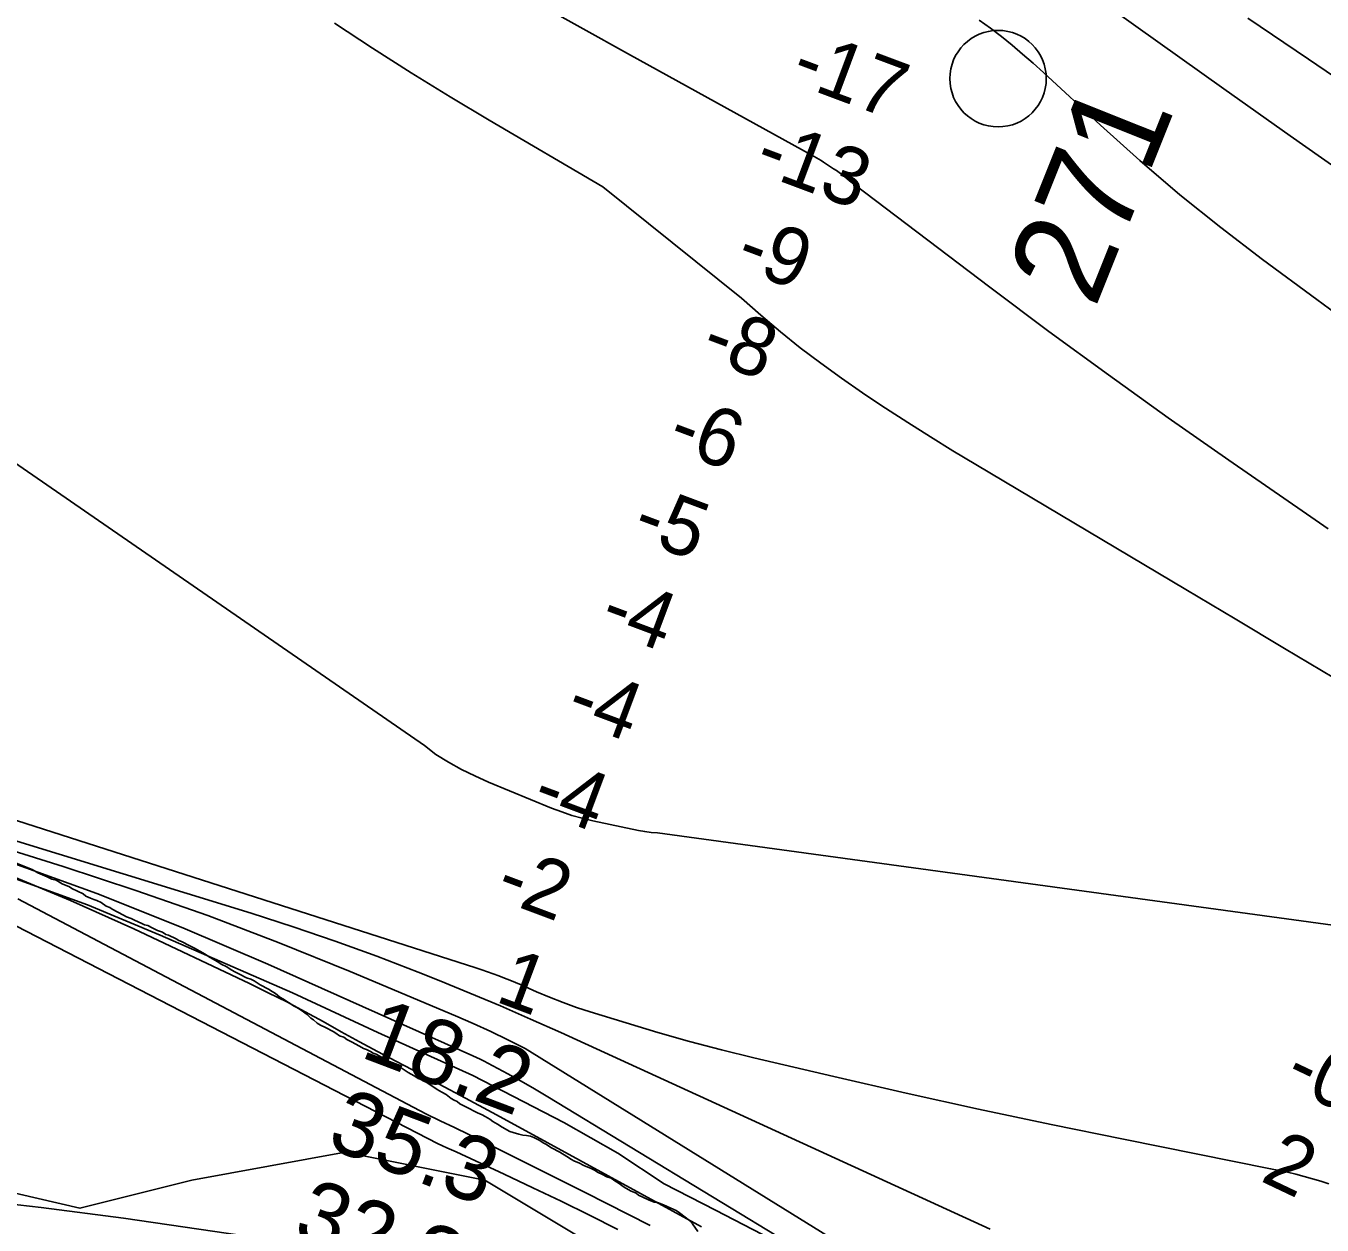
# Model space of a CAD drawing. Extents: x 3219052 to 3256913, y 800770 to 826146.
# Drawn here: x 3236049 to 3237393, y 814457 to 815700 of the extents above; entities that cross this region are included whole.
import ezdxf

# ---------------------------------------------------------------- set-up
doc = ezdxf.new("R2010")
doc.units = 0
for name, color, linetype in [('V-RIVR-EDGE', 7, 'Continuous'), ('V-RIVR-IDEN', 7, 'Continuous'), ('V-RIVR-MILE', 7, 'Continuous'), ('V-RIVR-RANG', 7, 'Continuous'), ('V-SITE-VEGE', 7, 'Continuous'), ('V-TOPO-DPTH', 7, 'Continuous'), ('V-TOPO-MAJR', 7, 'Continuous'), ('V-TOPO-MINR', 7, 'Continuous'), ('V-TOPO-WATR', 7, 'Continuous'), ('V-WETL-SWMP', 7, 'Continuous')]:
    doc.layers.add(name, color=color, linetype=linetype)

msp = doc.modelspace()

# ---------------------------------------------------------------- linework, layer by layer
at = {"layer": 'V-RIVR-EDGE'}
msp.add_lwpolyline([(3235863.8, 814861.9), (3235960.2, 814843.9), (3236019.4, 814823.2), (3236113.4, 814789.3), (3236188.5, 814757.9), (3236325.9, 814697.9), (3236414.4, 814656.9), (3236512.7, 814612.4), (3236607.1, 814563.5), (3236663.1, 814531.8), (3236711.3, 814500), (3236764.2, 814472.6), (3236841.6, 814432.5)], dxfattribs=at)
at = {"layer": 'V-RIVR-MILE'}
msp.add_circle((3237057.3, 815645.8), 50, dxfattribs=at)
at = {"layer": 'V-SITE-VEGE'}
for points in [[(3236039.3, 814832.5), (3236050.8, 814828), (3236056, 814825.7), (3236061.8, 814822.5), (3236071.4, 814818.4), (3236076.2, 814815.7), (3236080.9, 814814.8), (3236087.2, 814811.1), (3236094.8, 814808), (3236097.2, 814806.1), (3236108.7, 814800.6), (3236111.6, 814798.3), (3236116.4, 814796), (3236119.8, 814794.7), (3236123.1, 814793.8), (3236127.4, 814791.5), (3236132.7, 814787.8), (3236136.6, 814786.4), (3236139, 814784.6), (3236150.5, 814778.6), (3236153.8, 814776.8), (3236158.6, 814775), (3236162, 814773.2), (3236169.6, 814770), (3236172.5, 814768.6), (3236175.8, 814767.7), (3236180.2, 814765.4), (3236185.9, 814762.7), (3236191.2, 814760.9), (3236194.5, 814758.6), (3236197.4, 814757.7), (3236205.1, 814754), (3236208, 814752.2), (3236210.8, 814751.3), (3236219.5, 814746.7), (3236224.2, 814744.4), (3236232.9, 814739.4), (3236236.2, 814737.5), (3236238.7, 814735.7), (3236247.8, 814730.6), (3236252.6, 814727.4), (3236256.9, 814725.1), (3236263.1, 814721.4), (3236266, 814719.6), (3236270.8, 814717.3), (3236278, 814713.6), (3236282.8, 814712.3), (3236286.1, 814710.5), (3236292.4, 814706.3), (3236301, 814701.7), (3236304.9, 814699.4), (3236308.2, 814697.1), (3236312.6, 814693.4), (3236315.9, 814691.6), (3236327.5, 814684.2), (3236330.3, 814682.8), (3236334.7, 814680), (3236340.9, 814675.4), (3236344.8, 814671.7), (3236347.7, 814669.8), (3236351.5, 814666.6), (3236354.9, 814664.3), (3236360.2, 814662), (3236367.9, 814657.9), (3236370.7, 814656), (3236374.6, 814653.3), (3236378.9, 814651.9), (3236382.3, 814649.6), (3236387.1, 814647.3), (3236395.2, 814642.7), (3236399.5, 814640.4), (3236402.4, 814639.1), (3236406.7, 814637.3), (3236409.6, 814635.4), (3236412.5, 814634.5), (3236415.8, 814632.7), (3236427.8, 814625.8), (3236434.5, 814622.1), (3236437.4, 814620.8), (3236445.6, 814615.2)], [(3236445.6, 814615.2), (3236451.8, 814612), (3236456.1, 814609.2), (3236461.9, 814607), (3236465.2, 814605.1), (3236475.8, 814597.7), (3236480.6, 814595), (3236485, 814592.7), (3236490.3, 814588.5), (3236493.6, 814586.7), (3236496.5, 814585.3), (3236499.4, 814583), (3236505.6, 814579.8), (3236517.6, 814573.4), (3236522.4, 814571.6), (3236525.7, 814569.7), (3236530.5, 814567), (3236533.4, 814564.6), (3236538.2, 814561.9), (3236543.1, 814558.7), (3236551.2, 814554.1), (3236554.6, 814553.2), (3236560.3, 814551.4), (3236564.6, 814550.5), (3236568.4, 814550.1), (3236572.7, 814549.3), (3236576, 814547.9), (3236582.3, 814544.7), (3236585.6, 814542.4), (3236588.5, 814541), (3236594.3, 814537.3), (3236602.9, 814532.7), (3236605.8, 814530.9), (3236612, 814527.2), (3236614.4, 814525.4), (3236618.3, 814523.5), (3236622.6, 814521.7), (3236627.8, 814519), (3236635.5, 814515.8), (3236638.9, 814514), (3236642.7, 814511.6), (3236646.5, 814509.8), (3236651.8, 814507.1), (3236656.1, 814505.7), (3236660, 814503), (3236663.3, 814501.1), (3236669.6, 814496.5), (3236676.3, 814492.8), (3236682.1, 814490.1), (3236684.5, 814488.2), (3236695, 814483.2), (3236700.7, 814480.9), (3236704.1, 814480.5), (3236710.3, 814478.3), (3236718, 814474.6), (3236723.7, 814472.4), (3236727.1, 814470), (3236734.3, 814464.5), (3236737.7, 814461.7), (3236740.6, 814458.4), (3236746, 814450.5)]]:
    msp.add_lwpolyline(points, dxfattribs=at)
at = {"layer": 'V-TOPO-DPTH'}
for points in [[(3237108.9, 815765.4), (3237223.1, 815683.8), (3237291.5, 815635.1), (3237360, 815586.6), (3237428.6, 815538.3)], [(3237428.6, 815538.3), (3237360, 815586.6), (3237291.5, 815635.1), (3237223.1, 815683.8), (3237108.9, 815765.4)], [(3236581.3, 815722.9), (3236627.3, 815697.4), (3236673.3, 815672), (3236866.6, 815565.2), (3236869.1, 815563.8), (3236871.5, 815562.4), (3236873.9, 815560.9), (3236876.3, 815559.3), (3236886.8, 815552.3), (3236889.7, 815550.4), (3236892.5, 815548.4), (3236895.3, 815546.3), (3236898, 815544.2), (3236900.7, 815542), (3236903.4, 815539.9), (3236906.2, 815537.8), (3236908.9, 815535.7), (3237048.9, 815429.6), (3237110.1, 815383.8), (3237171.7, 815338.6), (3237233.8, 815294.2), (3237296.4, 815250.3), (3237377.1, 815194.5), (3237399.6, 815178.9)], [(3237399.6, 815178.9), (3237377.1, 815194.5), (3237296.4, 815250.3), (3237233.8, 815294.2), (3237171.7, 815338.6), (3237110.1, 815383.8), (3237048.9, 815429.6), (3236908.9, 815535.7), (3236906.2, 815537.8), (3236903.4, 815539.9), (3236900.7, 815542), (3236898, 815544.2), (3236895.3, 815546.3), (3236892.5, 815548.4), (3236889.7, 815550.4), (3236886.8, 815552.3), (3236876.3, 815559.3), (3236873.9, 815560.9), (3236871.5, 815562.4), (3236869.1, 815563.8), (3236866.6, 815565.2), (3236673.3, 815672), (3236627.3, 815697.4), (3236581.3, 815722.9)], [(3237037.7, 815706.4), (3237049.3, 815698.1), (3237060.7, 815689.4), (3237071.9, 815680.4), (3237082.8, 815671.1), (3237093.6, 815661.7), (3237104.3, 815652), (3237163.4, 815597.4), (3237204.1, 815561), (3237245.6, 815525.5), (3237288.2, 815491.4), (3237331.6, 815458.3), (3237387.8, 815416.7), (3237414.1, 815397.5)], [(3237414.1, 815397.5), (3237387.8, 815416.7), (3237331.6, 815458.3), (3237288.2, 815491.4), (3237245.6, 815525.5), (3237204.1, 815561), (3237163.4, 815597.4), (3237104.3, 815652), (3237093.6, 815661.7), (3237082.8, 815671.1), (3237071.9, 815680.4), (3237060.7, 815689.4), (3237049.3, 815698.1), (3237037.7, 815706.4)], [(3237444.8, 814762.7), (3236704.3, 814863.9), (3236697.6, 814864.3), (3236691, 814865.1), (3236684.5, 814866.3), (3236637.2, 814876.2), (3236626.3, 814878.9), (3236615.5, 814881.9), (3236604.9, 814885.5), (3236594.4, 814889.5), (3236529, 814916.5), (3236514.9, 814922.8), (3236501.1, 814929.6), (3236487.6, 814937.2), (3236474.5, 814945.2), (3236462.6, 814954.5), (3235919.2, 815329.5)], [(3235919.2, 815329.5), (3236462.6, 814954.5), (3236474.5, 814945.2), (3236487.6, 814937.2), (3236501.1, 814929.6), (3236514.9, 814922.8), (3236529, 814916.5), (3236594.4, 814889.5), (3236604.9, 814885.5), (3236615.5, 814881.9), (3236626.3, 814878.9), (3236637.2, 814876.2), (3236684.5, 814866.3), (3236691, 814865.1), (3236697.6, 814864.3), (3236704.3, 814863.9), (3237444.8, 814762.7)], [(3237049.1, 814452.9), (3236603.9, 814656.7), (3236572.7, 814670.8), (3236541.3, 814684.5), (3236509.7, 814697.7), (3236478, 814710.7), (3236456.2, 814719.4), (3236413.3, 814735.9), (3236370.2, 814751.7), (3236326.6, 814766.5), (3236282.9, 814780.5), (3235818.3, 814923.4), (3235791.4, 814931.3), (3235764.3, 814938.9), (3235737.1, 814945.9), (3235709.8, 814952.4), (3235003.1, 815114.3), (3235000.1, 815115), (3234997.2, 815115.6)], [(3237049.1, 814452.9), (3236603.9, 814656.7), (3236572.7, 814670.8), (3236541.3, 814684.5), (3236509.7, 814697.7), (3236478, 814710.7), (3236456.2, 814719.4), (3236413.3, 814735.9), (3236370.2, 814751.7), (3236326.6, 814766.5), (3236282.9, 814780.5), (3235818.3, 814923.4), (3235791.4, 814931.3), (3235764.3, 814938.9), (3235737.1, 814945.9), (3235709.8, 814952.4), (3235155.6, 815079.4)], [(3235314.7, 815015), (3235399.2, 814999.2), (3235483.6, 814982), (3235722.4, 814930.3), (3235740.9, 814926), (3235759.2, 814921.4), (3235777.4, 814916.3), (3235795.5, 814910.8), (3235942.2, 814864.1), (3236033, 814833.5), (3236123.1, 814800.8), (3236212, 814765.2), (3236300.1, 814727.6), (3236512.7, 814632.7), (3236516.6, 814630.9), (3236520.5, 814629.1), (3236524.4, 814627.2), (3236528.2, 814625.2), (3236548.9, 814614.1), (3236562.9, 814606.4), (3236576.8, 814598.5), (3236590.6, 814590.2), (3236931.9, 814382.9)]]:
    msp.add_lwpolyline(points, dxfattribs=at)
at = {"layer": 'V-TOPO-MAJR'}
for points in [[(3237316.3, 815708.4), (3237379.1, 815666), (3237441.8, 815623.4)], [(3235889.9, 814844.1), (3236476.3, 814541.6), (3236481.2, 814539.5), (3236486, 814537.4), (3236490.8, 814535.2), (3236495.6, 814533), (3236545.4, 814509.9), (3236575, 814495.9), (3236604.4, 814481.8), (3236633.8, 814467.4), (3236663.1, 814452.7)], [(3236385, 814430), (3236150.6, 814464.3), (3236065.4, 814475.4), (3235980.1, 814484.9)]]:
    msp.add_lwpolyline(points, dxfattribs=at)
at = {"layer": 'V-TOPO-MINR'}
for points in [[(3237108.9, 815765.4), (3237223.1, 815683.8), (3237291.5, 815635.1), (3237360, 815586.6), (3237428.6, 815538.3)], [(3236581.3, 815722.9), (3236627.3, 815697.4), (3236673.3, 815672), (3236866.6, 815565.2), (3236869.1, 815563.8), (3236871.5, 815562.4), (3236873.9, 815560.9), (3236876.3, 815559.3), (3236886.8, 815552.3), (3236889.7, 815550.4), (3236892.5, 815548.4), (3236895.3, 815546.3), (3236898, 815544.2), (3236900.7, 815542), (3236903.4, 815539.9), (3236906.2, 815537.8), (3236908.9, 815535.7), (3237048.9, 815429.6), (3237110.1, 815383.8), (3237171.7, 815338.6), (3237233.8, 815294.2), (3237296.4, 815250.3), (3237377.1, 815194.5), (3237399.6, 815178.9)], [(3237037.7, 815706.4), (3237049.3, 815698.1), (3237060.7, 815689.4), (3237071.9, 815680.4), (3237082.8, 815671.1), (3237093.6, 815661.7), (3237104.3, 815652), (3237163.4, 815597.4), (3237204.1, 815561), (3237245.6, 815525.5), (3237288.2, 815491.4), (3237331.6, 815458.3), (3237387.8, 815416.7), (3237414.1, 815397.5)], [(3236369.2, 815703.4), (3236408.8, 815677.4), (3236448.8, 815651.8), (3236489.2, 815627), (3236529.8, 815602.6), (3236647.7, 815533.5), (3236791.4, 815418.2), (3236811.2, 815400.4), (3236831.6, 815383.4), (3236852.3, 815366.8), (3236873.6, 815350.7), (3236895.1, 815335.1), (3236916.9, 815319.9), (3236939, 815305.1), (3236940.6, 815304.1), (3236963.8, 815289.2), (3236987.1, 815274.4), (3237010.5, 815260), (3237034.1, 815245.8), (3237251.9, 815116.2), (3237303, 815085.7), (3237354.2, 815055.1), (3237405.3, 815024.4)], [(3235919.2, 815329.5), (3236462.6, 814954.5), (3236474.5, 814945.2), (3236487.6, 814937.2), (3236501.1, 814929.6), (3236514.9, 814922.8), (3236529, 814916.5), (3236594.4, 814889.5), (3236604.9, 814885.5), (3236615.5, 814881.9), (3236626.3, 814878.9), (3236637.2, 814876.2), (3236684.5, 814866.3), (3236691, 814865.1), (3236697.6, 814864.3), (3236704.3, 814863.9), (3237444.8, 814762.7)], [(3235847.4, 814938.2), (3236516, 814723.9), (3236522, 814721.9), (3236527.9, 814719.9), (3236533.8, 814717.8), (3236539.7, 814715.6), (3236545.5, 814713.3), (3236551.3, 814711), (3236557.1, 814708.6), (3236562.8, 814706.1), (3236578.7, 814699.1), (3236592.4, 814693.4), (3236606.3, 814687.9), (3236620.4, 814682.9), (3236634.5, 814678.3), (3236671.6, 814666.7), (3236704.5, 814656.9), (3236737.5, 814647.5), (3236770.7, 814638.8), (3236804, 814630.6), (3236886.9, 814611.3), (3236961.9, 814594.1), (3237037, 814577.4), (3237112.2, 814561.5), (3237187.5, 814546.1), (3237339.9, 814515.6), (3237348.6, 814513.8), (3237357.3, 814511.9), (3237366, 814509.8), (3237374.6, 814507.5), (3237383.2, 814505.1), (3237391.8, 814502.6), (3237400.3, 814499.8)], [(3235806.9, 814917), (3236088, 814828.9), (3236163.3, 814804.1), (3236238, 814778), (3236312, 814749.7), (3236385.5, 814720), (3236494.8, 814674), (3236513.1, 814666.1), (3236531.3, 814657.8), (3236549.2, 814649.2), (3236567.1, 814640.2), (3237045.1, 814344.2)], [(3236033, 814833.5), (3236123.1, 814800.8), (3236212, 814765.2), (3236300.1, 814727.6), (3236512.7, 814632.7), (3236516.6, 814630.9), (3236520.5, 814629.1), (3236524.4, 814627.2), (3236528.2, 814625.2), (3236548.9, 814614.1), (3236562.9, 814606.4), (3236576.8, 814598.5), (3236590.6, 814590.2), (3236931.9, 814382.9)], [(3236029.3, 814821.4), (3236095.6, 814793.7), (3236161.2, 814764.3), (3236281.3, 814707.5), (3236300.6, 814698.1), (3236319.8, 814688.5), (3236338.8, 814678.4), (3236357.6, 814668.1), (3236376.4, 814657.7), (3236395.2, 814647.3), (3236414.1, 814637.2), (3236433.1, 814627.1), (3236450.3, 814618), (3236477.8, 814603.4), (3236505.3, 814588.8), (3236532.8, 814574), (3236560.1, 814559.1), (3236750, 814455.4)], [(3236041.1, 814795.4), (3236464.1, 814572.4), (3236479, 814565.3), (3236493.8, 814558.2), (3236508.6, 814551), (3236523.4, 814543.7), (3236629.2, 814490.8), (3236696.7, 814456.8)]]:
    msp.add_lwpolyline(points, dxfattribs=at)
at = {"layer": 'V-TOPO-WATR'}
msp.add_lwpolyline([(3235818.3, 814923.4), (3236282.9, 814780.5), (3236326.6, 814766.5), (3236370.2, 814751.7), (3236413.3, 814735.9), (3236456.2, 814719.4), (3236478, 814710.7), (3236509.7, 814697.7), (3236541.3, 814684.5), (3236572.7, 814670.8), (3236603.9, 814656.7), (3237049.1, 814452.9)], dxfattribs=at)
at = {"layer": 'V-WETL-SWMP'}
msp.add_lwpolyline([(3234774.2, 814329.8), (3234803.2, 814518.1), (3234817.6, 814634), (3234629.5, 814735.4), (3234282.2, 814735.4), (3234253.3, 814822.3), (3234398, 814880.2), (3234644, 814909.2), (3234803.2, 814851.2), (3234991.3, 814735.4), (3235121.5, 814648.5), (3235309.6, 814619.5), (3235454.3, 814619.5), (3235642.4, 814576), (3235917.4, 814518.1), (3236105.5, 814474.7), (3236221.3, 814503.6), (3236380.5, 814532.6), (3236525.2, 814503.6), (3236742.2, 814373.3)], dxfattribs=at)

# ---------------------------------------------------------------- texts
at = {"layer": 'V-RIVR-IDEN'}
msp.add_text('271', height=100, rotation=68.21, dxfattribs=at).set_placement((3237157.7, 815406.5))
at = {"layer": 'V-RIVR-RANG'}
for s, height, rotation, p in [('-17', 60, 339.4799, (3236840.1, 815642.9)), ('-13', 60, 339.4799, (3236802.2, 815550.3)), ('-9', 60, 339.4799, (3236782.7, 815450.8)), ('-8', 60, 339.4799, (3236746.8, 815357.5)), ('-6', 60, 339.4799, (3236712.1, 815263.7)), ('-5', 60, 339.4799, (3236675.5, 815170.6)), ('-4', 60, 339.4799, (3236641.9, 815076.5)), ('-4', 60, 339.4799, (3236606.7, 814982.9)), ('-4', 60, 339.4799, (3236571.5, 814889.3)), ('-2', 60, 339.4799, (3236533.8, 814796.6)), ('1', 60, 339.4799, (3236534.7, 814689.5)), ('18.2', 67, 339.2483, (3236394.7, 814631.9)), ('-0', 60, 334.5607, (3237351.3, 814603.1)), ('35.3', 67, 339.2483, (3236359.5, 814538.3)), ('2', 60, 334.5607, (3237327.9, 814503.5)), ('32.3', 67, 339.2483, (3236324.2, 814444.7))]:
    msp.add_text(s, height=height, rotation=rotation, dxfattribs=at).set_placement(p)

doc.saveas('drawing.dxf')
